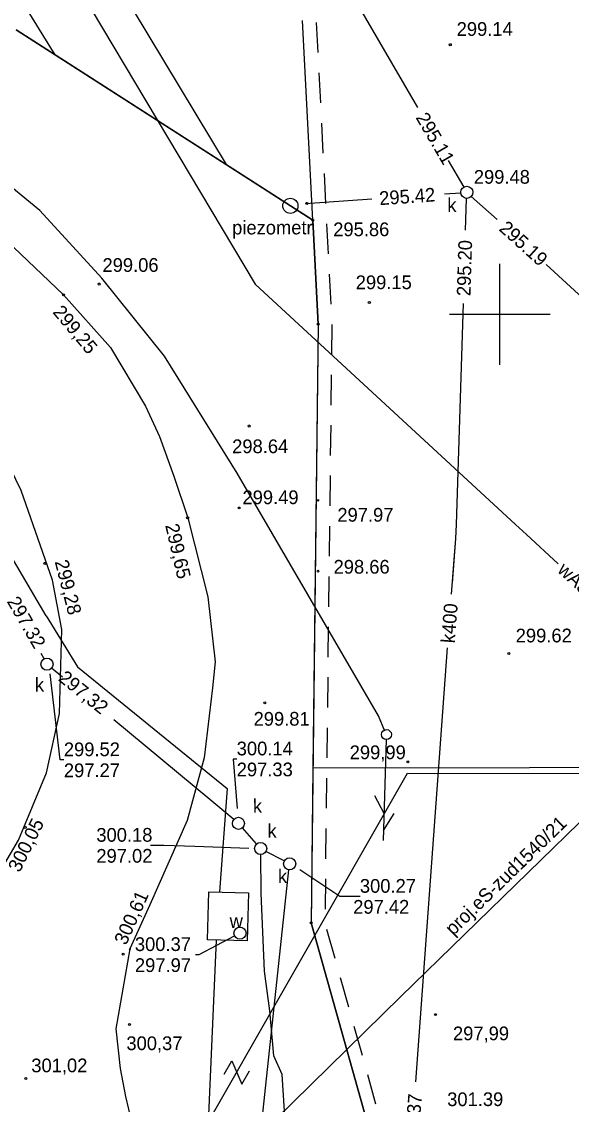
# Model space of a CAD drawing. Extents: x 7477803 to 7478145, y 5500698 to 5500984.
# Drawn here: x 7478026.3 to 7478053.5, y 5500810.8 to 5500864.5 of the extents above; entities that cross this region are included whole.
import ezdxf

# ---------------------------------------------------------------- set-up
doc = ezdxf.new("R2010")
doc.units = 0
for name, color, linetype in [('203-Punkt załamania granicy działki nie stabilizowany', 7, 'Continuous'), ('e_Proj', 7, 'Continuous'), ('e_slupy', 7, 'Continuous'), ('eNN', 7, 'Continuous'), ('gr_dzialki', 7, 'Continuous'), ('gr_klasy', 7, 'Continuous'), ('gr_uzytek', 7, 'Continuous'), ('jezdnia', 7, 'Continuous'), ('k', 7, 'Continuous'), ('k_elem_naziemne', 7, 'Continuous'), ('k_opis', 7, 'Continuous'), ('k_rzedne', 7, 'Continuous'), ('kraweznik', 7, 'Continuous'), ('ogr_symb', 7, 'Continuous'), ('pkt_wys', 7, 'Continuous'), ('pob_gr_obrebu', 7, 'Continuous'), ('przehaczenie', 7, 'Continuous'), ('robocza38', 7, 'Continuous'), ('robocza49', 7, 'Continuous'), ('t_slupy', 7, 'Continuous'), ('w', 7, 'Continuous'), ('w_elem_naziemne', 7, 'Continuous'), ('w_opis', 7, 'Continuous'), ('w_rzedne', 7, 'Continuous')]:
    doc.layers.add(name, color=color, linetype=linetype)

# ---------------------------------------------------------------- blocks, each defined once
blk = doc.blocks.new('203')
blk.add_circle((0, 0), 0.045)
blk = doc.blocks.new('506_1')
at = {"layer": 'w_elem_naziemne'}
blk.add_circle((0, 0), 0.3, dxfattribs=at)
blk = doc.blocks.new('506_5')
at = {"layer": 'k_elem_naziemne'}
blk.add_circle((0, 0), 0.3, dxfattribs=at)
blk = doc.blocks.new('511_5_1')
at = {"layer": 'e_slupy'}
blk.add_circle((0, 0), 0.25, dxfattribs=at)
blk = doc.blocks.new('506_5_1')
at = {"layer": 'k_elem_naziemne'}
blk.add_circle((0, 0), 0.3, dxfattribs=at)
blk = doc.blocks.new('506')
at = {"layer": 'robocza38'}
blk.add_circle((0, 0), 0.3, dxfattribs=at)
blk = doc.blocks.new('511_5_2')
at = {"layer": 't_slupy'}
blk.add_circle((0, 0), 0.25, dxfattribs=at)
blk = doc.blocks.new('SUPT01')
at = {"layer": 't_slupy'}
for p, q in [((5, 0), (105, 0)), ((60.7, -10), (78, 0)), ((95.3, 0), (78, 10))]:
    blk.add_line(p, q, dxfattribs=at)
blk = doc.blocks.new('SUPT1')
at = {"layer": 't_slupy', "xscale": 0.05000000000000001, "yscale": 0.05000000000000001}
blk.add_blockref('SUPT01', (0, 0), dxfattribs=at)
blk = doc.blocks.new('140_1')
at = {"layer": 'pkt_wys'}
blk.add_circle((0, 0), 0.045, dxfattribs=at)
blk.add_circle((0, 0), 0.045, dxfattribs=at)
blk = doc.blocks.new('801_1')
at = {"layer": 'pkt_wys'}
blk.add_circle((0, 0), 0.045, dxfattribs=at)
blk.add_circle((0, 0), 0.045, dxfattribs=at)
blk = doc.blocks.new('801_5')
at = {"layer": 'pkt_wys'}
blk.add_circle((0, 0), 0.05, dxfattribs=at)
blk.add_circle((0, 0), 0.05, dxfattribs=at)
blk = doc.blocks.new('991_5_1')
at = {"layer": 'przehaczenie'}
blk.add_lwpolyline([(-0.38, 0.5), (0.38, 0.5), (-0.38, -0.5), (0.38, -0.5)], dxfattribs=at)
blk = doc.blocks.new('801_5_2')
at = {"layer": 'pkt_wys'}
blk.add_circle((0, 0), 0.05, dxfattribs=at)
blk.add_circle((0, 0), 0.05, dxfattribs=at)
blk = doc.blocks.new('801_5_3')
at = {"layer": 'pkt_wys'}
blk.add_circle((0, 0), 0.05, dxfattribs=at)
blk.add_circle((0, 0), 0.05, dxfattribs=at)

msp = doc.modelspace()

# ---------------------------------------------------------------- linework, layer by layer
at = {"layer": 'e_Proj'}
msp.add_lwpolyline([(7478085.721, 5500828.46), (7478062.59, 5500828.394), (7478057.723, 5500828.457), (7478045.093, 5500816.16), (7478029.949, 5500801.309), (7478024.948, 5500777.245), (7478020.357, 5500757.697), (7478013.921, 5500735.554), (7478010.536, 5500720.256)], dxfattribs=at)
at = {"layer": 'eNN'}
for points in [[(7478044.292, 5500829.332), (7478043.979, 5500830.08), (7478036.967, 5500842.126), (7478033.374, 5500847.92), (7478030.266, 5500851.792), (7478027.179, 5500855.154), (7478025.031, 5500856.9), (7478008.369, 5500866.572), (7477997.07, 5500873.297), (7477990.438, 5500877.31), (7477980.374, 5500883.358), (7477966.627, 5500891.122), (7477956.111, 5500897.36), (7477948.099, 5500902.324), (7477944.454, 5500904.573)], [(7478039.511, 5500808.891), (7478039.356, 5500809.972), (7478039.208, 5500812.294), (7478038.785, 5500813.23), (7478038.592, 5500815.458), (7478038.326, 5500817.428), (7478038.16, 5500821.296), (7478038.14, 5500823.204)]]:
    msp.add_lwpolyline(points, dxfattribs=at)
at = {"layer": 'gr_dzialki'}
for points in [[(7478040.72, 5500854.66), (7478040.21, 5500864.57)], [(7478040.72, 5500854.66), (7478026.01, 5500864.11)], [(7478040.99, 5500849.51), (7478040.72, 5500854.66)], [(7478040.99, 5500849.51), (7478040.64, 5500819.82)], [(7478044.33, 5500806.69), (7478040.64, 5500819.82)]]:
    msp.add_lwpolyline(points, dxfattribs=at)
at = {"layer": 'gr_klasy'}
for points in [[(7477998.73, 5500919.96), (7478036.42, 5500857.42)], [(7478027.95, 5500862.87), (7477997.16, 5500912.65)], [(7478040.72, 5500854.66), (7478040.21, 5500864.57)], [(7478026.01, 5500864.11), (7478027.95, 5500862.87)], [(7478036.42, 5500857.42), (7478040.72, 5500854.66)], [(7478040.72, 5500854.66), (7478040.99, 5500849.51)], [(7478040.99, 5500849.51), (7478040.73, 5500827.51)], [(7478040.73, 5500827.51), (7478083.71, 5500827.57)]]:
    msp.add_lwpolyline(points, dxfattribs=at)
at = {"layer": 'gr_uzytek'}
msp.add_line((7478027.95, 5500862.87), (7478036.42, 5500857.42), dxfattribs=at)
msp.add_lwpolyline([(7478040.73, 5500827.51), (7478040.64, 5500819.82), (7478044.33, 5500806.69), (7478044.2, 5500803.44)], dxfattribs=at)
at = {"layer": 'jezdnia'}
for points in [[(7478012.783, 5500862.5), (7478017.927, 5500859.186), (7478021.58, 5500856.7), (7478025.873, 5500853.334), (7478028.356, 5500850.967), (7478030.699, 5500848.349), (7478032.422, 5500845.441), (7478033.114, 5500843.932), (7478033.826, 5500841.963), (7478034.518, 5500839.904), (7478035.522, 5500835.985), (7478035.876, 5500832.755), (7478035.757, 5500831.475), (7478035.341, 5500827.995), (7478034.495, 5500824.894), (7478032.649, 5500820.712), (7478031.642, 5500818.53)], [(7478008.149, 5500811.845), (7478011.769, 5500811.909), (7478014.098, 5500812.451), (7478017.047, 5500813.895), (7478021.153, 5500817.039), (7478024.239, 5500820.732), (7478026.136, 5500823.914), (7478027.522, 5500827.266), (7478028.159, 5500830.207), (7478028.284, 5500834.367), (7478027.822, 5500836.806), (7478026.257, 5500841.255), (7478025.204, 5500843.403), (7478022.901, 5500846.211), (7478018.407, 5500849.956), (7478013.603, 5500853.721), (7478010.61, 5500855.711)]]:
    msp.add_lwpolyline(points, dxfattribs=at)
at = {"layer": 'k'}
for p, q in [((7478047.439, 5500857.631), (7478048.21, 5500856.308)), ((7478040.355, 5500855.495), (7478043.645, 5500855.722)), ((7478047.257, 5500855.972), (7478048.061, 5500856.028)), ((7478048.302, 5500854.166), (7478048.351, 5500855.749)), ((7478047.852, 5500839.568), (7478048.19, 5500850.526)), ((7478027.399, 5500832.91), (7478027.255, 5500833.17)), ((7478028.318, 5500832.001), (7478027.77, 5500832.457)), ((7478035.621, 5500825.928), (7478030.86, 5500829.887)), ((7478036.803, 5500824.944), (7478035.621, 5500825.928)), ((7478037.938, 5500823.729), (7478037.233, 5500824.527)), ((7478039.309, 5500822.887), (7478038.402, 5500823.364)), ((7478038.159, 5500809.5), (7478039.543, 5500822.449))]:
    msp.add_line(p, q, dxfattribs=at)
for points in [[(7478020.436, 5500903.997), (7478021.747, 5500901.762), (7478045.913, 5500860.252)], [(7478049.862, 5500854.697), (7478048.583, 5500855.848)], [(7478057.09, 5500848.054), (7478054.513, 5500850.429), (7478052.301, 5500852.476)], [(7478047.608, 5500836.123), (7478047.823, 5500838.882), (7478047.852, 5500839.568)], [(7478047.65, 5500836.669), (7478047.823, 5500838.882), (7478047.852, 5500839.568)], [(7478045.83, 5500811.929), (7478047.4, 5500833.461)]]:
    msp.add_lwpolyline(points, dxfattribs=at)
at = {"layer": 'k_rzedne'}
for points in [[(7478028.378, 5500827.902), (7478028.198, 5500827.902), (7478027.693, 5500832.175)], [(7478036.95, 5500827.944), (7478036.77, 5500827.943), (7478036.969, 5500825.484)], [(7478032.679, 5500823.663), (7478033.336, 5500823.664), (7478034.868, 5500823.614)], [(7478034.868, 5500823.614), (7478037.558, 5500823.525)], [(7478043.067, 5500821.13), (7478042.066, 5500821.123), (7478040.078, 5500822.453)]]:
    msp.add_lwpolyline(points, dxfattribs=at)
at = {"layer": 'kraweznik'}
msp.add_lwpolyline([(7478031.642, 5500818.53), (7478030.948, 5500814.555), (7478031.177, 5500812.591), (7478031.438, 5500811.212), (7478031.879, 5500809.329), (7478032.326, 5500808.404), (7478033.001, 5500807.187), (7478034.212, 5500806.19), (7478036.657, 5500804.456), (7478039.373, 5500803.842)], dxfattribs=at)
at = {"layer": 'ogr_symb'}
msp.add_lwpolyline([(7478026.319, 5500802.715), (7478028.17, 5500804.079), (7478034.551, 5500808.191), (7478045.422, 5500827.246), (7478069.852, 5500827.202)], dxfattribs=at)
at = {"layer": 'pkt_wys'}
msp.add_lwpolyline([(7478031.663, 5500818.57), (7478031.642, 5500818.53), (7478031.62, 5500818.491)], dxfattribs=at)
msp.add_lwpolyline([(7478031.663, 5500818.57), (7478031.642, 5500818.53), (7478031.62, 5500818.491)], dxfattribs=at)
msp.add_arc((7478031.642, 5500818.53), 0.045, 241.3817, 61.3817, dxfattribs=at)
msp.add_arc((7478031.642, 5500818.53), 0.045, 241.3817, 61.3817, dxfattribs=at)
at = {"layer": 'pob_gr_obrebu'}
for p, q in [((7478040.893, 5500864.477), (7478040.97, 5500862.979)), ((7478041.022, 5500861.98), (7478041.099, 5500860.482)), ((7478041.151, 5500859.484), (7478041.228, 5500857.986)), ((7478041.279, 5500856.987), (7478041.357, 5500855.489)), ((7478041.408, 5500854.49), (7478041.485, 5500852.992)), ((7478041.537, 5500851.994), (7478041.614, 5500850.496)), ((7478041.639, 5500846.997), (7478041.622, 5500845.497)), ((7478041.61, 5500844.497), (7478041.592, 5500842.997)), ((7478041.581, 5500841.998), (7478041.563, 5500840.498)), ((7478041.551, 5500839.498), (7478041.534, 5500837.998)), ((7478041.522, 5500836.998), (7478041.505, 5500835.498)), ((7478041.493, 5500834.498), (7478041.475, 5500832.998)), ((7478041.464, 5500831.998), (7478041.446, 5500830.498)), ((7478041.434, 5500829.498), (7478041.417, 5500827.998)), ((7478041.405, 5500826.999), (7478041.387, 5500825.499)), ((7478041.376, 5500824.499), (7478041.358, 5500822.999)), ((7478041.346, 5500821.999), (7478041.329, 5500820.499)), ((7478041.409, 5500819.511), (7478041.814, 5500818.067)), ((7478042.085, 5500817.104), (7478042.49, 5500815.66)), ((7478042.76, 5500814.697), (7478043.165, 5500813.253)), ((7478043.435, 5500812.29), (7478043.84, 5500810.846))]:
    msp.add_line(p, q, dxfattribs=at)
msp.add_lwpolyline([(7478041.666, 5500849.497), (7478041.668, 5500849.451), (7478041.651, 5500847.997)], dxfattribs=at)
at = {"layer": 'robocza49'}
for p, q in [((7478050, 5500847.5), (7478050, 5500852.5)), ((7478047.5, 5500850), (7478052.5, 5500850))]:
    msp.add_line(p, q, dxfattribs=at)
at = {"layer": 'w'}
for points in [[(7478024.653, 5500873.716), (7478028.65, 5500866.944), (7478037.871, 5500851.488), (7478050.775, 5500839.571), (7478051.315, 5500839.075), (7478052.898, 5500837.629)], [(7478027.498, 5500835.049), (7478025.026, 5500839.239)], [(7478027.498, 5500835.049), (7478029.059, 5500832.518), (7478035.942, 5500826.916)], [(7478035.942, 5500826.916), (7478036.469, 5500826.487), (7478036.101, 5500821.349)], [(7478035.933, 5500818.954), (7478035.292, 5500804.261), (7478034.872, 5500794.756), (7478033.904, 5500789.105), (7478028.928, 5500766.534)]]:
    msp.add_lwpolyline(points, dxfattribs=at)
at = {"layer": 'w_elem_naziemne'}
msp.add_lwpolyline([(7478037.538, 5500821.302), (7478037.469, 5500818.924), (7478035.507, 5500818.98), (7478035.575, 5500821.358)], close=True, dxfattribs=at)
at = {"layer": 'w_rzedne'}
msp.add_lwpolyline([(7478034.913, 5500818.243), (7478035.093, 5500818.244), (7478036.846, 5500819.167)], dxfattribs=at)

# ---------------------------------------------------------------- block references
at = {"layer": '203-Punkt załamania granicy działki nie stabilizowany'}
for p in [(7478040.72, 5500854.66), (7478040.99, 5500849.51), (7478040.64, 5500819.82)]:
    msp.add_blockref('203', p, dxfattribs=at)
at = {"layer": 'e_slupy', "rotation": 160.50967888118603}
msp.add_blockref('511_5_1', (7478044.375, 5500829.154), dxfattribs=at)
at = {"layer": 'k_elem_naziemne', "rotation": 0.0626175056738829}
for name, p in [('506_5_1', (7478048.361, 5500856.049)), ('506_5', (7478027.542, 5500832.647)), ('506_5', (7478037.034, 5500824.752)), ('506_5', (7478038.137, 5500823.504)), ('506_5', (7478039.575, 5500822.747))]:
    msp.add_blockref(name, p, dxfattribs=at)
at = {"layer": 'pkt_wys', "rotation": 0.0626175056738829}
for name, p in [('801_5', (7478047.543, 5500863.368)), ('801_5', (7478040.431, 5500855.5)), ('801_5', (7478030.126, 5500851.499)), ('801_5_2', (7478028.356, 5500850.967)), ('801_5', (7478043.527, 5500850.583)), ('801_5', (7478037.563, 5500844.457)), ('801_1', (7478040.967, 5500840.771)), ('801_1', (7478037.068, 5500840.396)), ('801_5_2', (7478034.518, 5500839.904)), ('801_5_2', (7478027.441, 5500837.646)), ('801_1', (7478040.981, 5500837.261)), ('801_5', (7478050.446, 5500833.171)), ('801_1', (7478038.348, 5500830.728)), ('140_1', (7478045.441, 5500827.8)), ('801_5_2', (7478026.455, 5500824.555)), ('801_5_2', (7478031.322, 5500818.26)), ('140_1', (7478046.81, 5500815.266)), ('140_1', (7478031.632, 5500814.775)), ('801_5_3', (7478026.489, 5500812.105))]:
    msp.add_blockref(name, p, dxfattribs=at)
at = {"layer": 'przehaczenie', "rotation": 60.23505089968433}
msp.add_blockref('991_5_1', (7478036.957, 5500812.4), dxfattribs=at)
at = {"layer": 'robocza38', "xscale": 1.2539698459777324, "yscale": 1.2539698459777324, "rotation": 0.06261750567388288}
msp.add_blockref('506', (7478039.611, 5500855.379), dxfattribs=at)
at = {"layer": 't_slupy'}
for name, rotation in [('511_5_2', 0.0626175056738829), ('SUPT1', -91.82447919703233)]:
    msp.add_blockref(name, (7478044.375, 5500829.154), dxfattribs=dict(at, rotation=rotation))
at = {"layer": 'w_elem_naziemne', "rotation": 0.0626175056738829}
msp.add_blockref('506_1', (7478037.112, 5500819.306), dxfattribs=at)

# ---------------------------------------------------------------- texts
at = {"layer": 'e_Proj'}
msp.add_text('proj.eS-zud1540/21', height=0.68, rotation=44.234, dxfattribs=at).set_placement((7478047.689, 5500819.156))
at = {"layer": 'k_elem_naziemne'}
for p in [(7478047.393, 5500855.075), (7478026.943, 5500831.291), (7478037.755, 5500825.277), (7478038.478, 5500824.04), (7478038.996, 5500821.789)]:
    msp.add_text('k', height=0.68, rotation=0.0626, dxfattribs=at).set_placement(p)
at = {"layer": 'k_opis'}
msp.add_text('k400', height=0.68, rotation=85.5397, dxfattribs=at).set_placement((7478047.761, 5500833.67))
at = {"layer": 'k_rzedne'}
for s, rotation, p in [('295.11', 300.2071, (7478045.808, 5500859.757)), ('295.42', 3.9582, (7478044.042, 5500855.409)), ('295.19', 317.9956, (7478049.913, 5500854.193)), ('295.20', 88.2313, (7478048.541, 5500850.89)), ('297.32', 300.0796, (7478025.534, 5500835.759)), ('297,32', 321.1172, (7478028.059, 5500831.864)), ('300.14', 0.0626, (7478036.95, 5500828.124)), ('299.52', 0.0626, (7478028.378, 5500828.082)), ('297.27', 0.0626, (7478028.379, 5500827.042)), ('297.33', 0.0626, (7478036.951, 5500827.084)), ('300.18', 0.0626, (7478029.989, 5500823.84)), ('297.02', 0.0626, (7478029.99, 5500822.8)), ('300.27', 0.0626, (7478043.058, 5500821.31)), ('297.42', 0.0626, (7478042.726, 5500820.27)), ('297,37', 85.5397, (7478045.925, 5500808.545)), ('301.39', 0.0626, (7478047.388, 5500810.729))]:
    msp.add_text(s, height=0.68, rotation=rotation, dxfattribs=at).set_placement(p)
at = {"layer": 'pkt_wys'}
for s, rotation, p in [('299.14', 0.0626, (7478047.859, 5500863.806)), ('299.48', 0.0626, (7478048.709, 5500856.472)), ('295.86', 0.0626, (7478041.737, 5500853.871)), ('299.06', 0.0626, (7478030.294, 5500852.101)), ('299.15', 0.0626, (7478042.853, 5500851.243)), ('299,25', 310.0312, (7478027.793, 5500850.092)), ('298.64', 0.0626, (7478036.725, 5500843.111)), ('299.49', 0.0626, (7478037.237, 5500840.581)), ('297.97', 0.0626, (7478041.942, 5500839.713)), ('299,65', 282.9926, (7478033.399, 5500839.536)), ('299,28', 284.3263, (7478027.921, 5500837.73)), ('298.66', 0.0626, (7478041.754, 5500837.135)), ('299.62', 0.0626, (7478050.786, 5500833.726)), ('299.81', 0.0626, (7478037.787, 5500829.595)), ('299,99', 0.0626, (7478042.554, 5500827.934)), ('300,05', 63.6643, (7478026.186, 5500822.281)), ('300,61', 65.8273, (7478031.464, 5500818.67)), ('297,99', 0.0626, (7478047.675, 5500813.994)), ('300,37', 0.0626, (7478031.479, 5500813.506)), ('301,02', 0.0626, (7478026.764, 5500812.406))]:
    msp.add_text(s, height=0.68, rotation=rotation, dxfattribs=at).set_placement(p)
at = {"layer": 'robocza38'}
msp.add_text('piezometr', height=0.68, rotation=0.0626, dxfattribs=at).set_placement((7478036.724, 5500853.958))
at = {"layer": 'w_elem_naziemne'}
msp.add_text('w', height=0.68, rotation=0.0626, dxfattribs=at).set_placement((7478036.6, 5500819.57))
at = {"layer": 'w_opis'}
msp.add_text('wA32', height=0.68, rotation=317.5858, dxfattribs=at).set_placement((7478052.81, 5500837.251))
at = {"layer": 'w_rzedne'}
for s, p in [('300.37', (7478031.901, 5500818.42)), ('297.97', (7478031.902, 5500817.38))]:
    msp.add_text(s, height=0.68, rotation=0.0626, dxfattribs=at).set_placement(p)

doc.saveas('drawing.dxf')
